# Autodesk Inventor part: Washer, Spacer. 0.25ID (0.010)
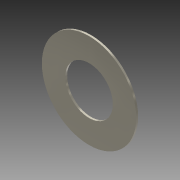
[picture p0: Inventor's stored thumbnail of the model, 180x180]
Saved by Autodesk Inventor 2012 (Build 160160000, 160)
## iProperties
Created: 2010-12
Part Number: Washer, Spacer. 0.25ID (0.010)
Document SubType Name: Modeling
Designer: Alex
Density: 7.84 g/cm^3
Mass: 0.188181 g
Surface Area: 2.0424 cm^2
Volume: 0.0240027 cm^3
Material: Steel, High Strength Low Alloy
Author: Alex
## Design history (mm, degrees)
sketch "Sketch1"
  geometry: C1 r 6.35 at (0, 0); 2 further points
  constraints: 1 centre point
  dimensions: "d0" = 12.7 diameter of C1
extrude "Extrusion1" new body sketch "Sketch1" distance "d1" = 0.254; taper "d2" = 0 deg
hole "Hole1" diameter "d5" = 6.4008; stored, may be unused: countersink angle "d9" = 82 deg, drill point angle "d11" = 118 deg; dims "d3" = 25.4, "d4" = 25.4, "d6" = 19.05, "d7" = 9.525, "d8" = 6.35, "d10" = 25.4
body "Solid1"
